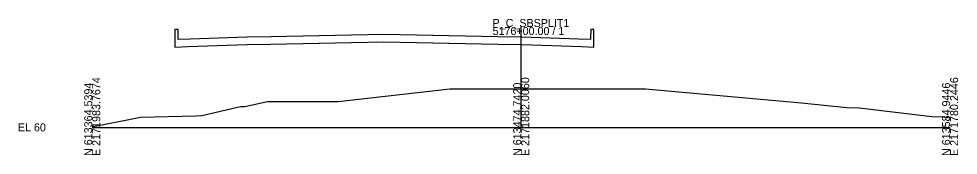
# Model space of a CAD drawing. Extents: x -26 to 1303, y -3010 to 12023.
# Drawn here: x -25.7 to 302.8, y 2490.3 to 2537.8 of the extents above; entities that cross this region are included whole.
import ezdxf

# ---------------------------------------------------------------- set-up
doc = ezdxf.new("R2010")
doc.units = 0
for name, color, linetype in [('RD_GPK_XS_Cell', 7, 'Continuous'), ('RD_PD_Final_TrvlWay', 7, 'Continuous'), ('RD_XS_ExGround', 7, 'Continuous')]:
    doc.layers.add(name, color=color, linetype=linetype)

msp = doc.modelspace()

# ---------------------------------------------------------------- linework, layer by layer
at = {"layer": 'RD_GPK_XS_Cell'}
for p, q in [((150, 2500), (150, 2535)), ((0, 2500), (150, 2500)), ((150, 2500), (300, 2500))]:
    msp.add_line(p, q, dxfattribs=at)
at = {"layer": 'RD_PD_Final_TrvlWay'}
msp.add_lwpolyline([(33.29, 2528.18), (54.1, 2528.89), (62.46, 2529.06), (102, 2529.85), (141.82, 2529.06), (150.22, 2528.89), (171.04, 2528.17), (175.43, 2528.02), (175.43, 2529.08), (175.43, 2534.11), (175.24, 2534.11), (174.31, 2534.11), (174.24, 2531.22), (174.22, 2530.61), (170.04, 2530.75), (150.22, 2531.45), (141.82, 2531.62), (102, 2532.41), (62.46, 2531.62), (54.1, 2531.45), (34.29, 2530.76), (30.1, 2530.61), (30.09, 2531.22), (30.02, 2534.11), (29.83, 2534.11), (28.9, 2534.11), (28.9, 2529.09), (28.9, 2528.02), (33.29, 2528.18)], dxfattribs=at)
at = {"layer": 'RD_XS_ExGround'}
msp.add_lwpolyline([(0, 2500.27), (0.41, 2500.27), (16.87, 2503.5), (36.17, 2503.98), (38.28, 2504.09), (51.87, 2507.23), (53.32, 2507.24), (61.3, 2509.02), (83.76, 2509.01), (86.04, 2509.02), (125.1, 2513.47), (128.18, 2513.47), (130.58, 2513.47), (132.08, 2513.47), (137.11, 2513.47), (146.34, 2513.47), (171.47, 2513.47), (173.26, 2513.47), (178.16, 2513.47), (178.94, 2513.47), (184.77, 2513.47), (189.21, 2513.47), (189.94, 2513.47), (193.47, 2513.47), (247.99, 2508.59), (263.94, 2506.96), (268.23, 2506.81), (293.61, 2503.83), (297.6, 2503.62), (300, 2503.38)], dxfattribs=at)

# ---------------------------------------------------------------- texts
at = {"layer": 'RD_GPK_XS_Cell'}
for s, p in [('P_C_SBSPLIT1', (140, 2535)), ('5176+00.00 / 1', (140, 2532.2)), ('EL 60', (-26, 2498.6))]:
    msp.add_text(s, height=2.8, dxfattribs=at).set_placement(p)
for s, p in [('E 2171983.7674', (2.8, 2490)), ('E 2171882.0060', (152.8, 2490)), ('E 2171780.2446', (302.8, 2490)), ('N 613364.5394', (0, 2490)), ('N 613474.7420', (150, 2490)), ('N 613584.9446', (300, 2490))]:
    msp.add_text(s, height=2.8, rotation=90, dxfattribs=at).set_placement(p)

doc.saveas('drawing.dxf')
